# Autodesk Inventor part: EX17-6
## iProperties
Created: 2006-05
Part Number: EX17-6
Document SubType Name: Modeling
Designer: M. MALLOY
Project: EVERGREEN VALLEY COLLEGE
Description: EXT. CLIP, AXIAL ROTOR CLIP
Authority: E. MOSS
Author: Mike Malloy
Title: EX17-6
Revision Number: A
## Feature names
1. Extrusion1
